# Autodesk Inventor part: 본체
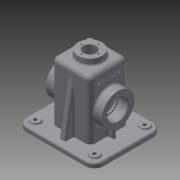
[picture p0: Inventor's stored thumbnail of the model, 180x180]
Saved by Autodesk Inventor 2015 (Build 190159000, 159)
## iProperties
Created: 2016-06
Part Number: 본체
Material: Generic
Document SubType Name: Modeling
Designer: Administrator
Density: 1 g/cm^3
Appearance: Default
Author: Administrator
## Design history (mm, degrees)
sketch "스케치1"
  geometry: L1 (-65, -57.5)-(65, -57.5); L2 (65, -57.5)-(65, 57.5); L3 (65, 57.5)-(-65, 57.5); L4 (-65, 57.5)-(-65, -57.5); L5 (-65, -57.5)-(65, 57.5); L6 (65, -57.5)-(-65, 57.5); 1 further point
  constraints: 12 end point, 2 midpoint, 2 parallel, 1 horizontal, 1 perpendicular
  dimensions: "d0" = 130 distance of L2.end L3.end; "d1" = 115 distance of L1.end L2.end
extrude "돌출1" new body sketch "스케치1" distance "d2" = 10; taper "d3" = 0 deg
fillet "모깎기1" dims "d4" = 15
fillet "모깎기2" dims "d5" = 3
sketch "스케치2"
  geometry: L1 (-50, 57.5)-(50, 57.5) reference; L2 (-65, -42.5)-(-65, 42.5) reference; L3 (50, -57.5)-(-50, -57.5) reference; L4 (65, 42.5)-(65, -42.5) reference; L5 (60, 42.5)-(60, -42.5); L6 (50, -52.5)-(-50, -52.5); L7 (-60, -42.5)-(-60, 42.5); L8 (-50, 52.5)-(50, 52.5); A1 r 15 centre (50, 42.5) between (65, 42.5) and (50, 57.5) reference; A2 r 15 centre (-50, 42.5) between (-50, 57.5) and (-65, 42.5) reference; A3 r 15 centre (-50, -42.5) between (-65, -42.5) and (-50, -57.5) reference; A4 r 15 centre (50, -42.5) between (50, -57.5) and (65, -42.5) reference; A5 r 10 centre (50, 42.5) between (60, 42.5) and (50, 52.5); A6 r 10 centre (50, -42.5) between (50, -52.5) and (60, -42.5); A7 r 10 centre (-50, -42.5) between (-60, -42.5) and (-50, -52.5); A8 r 10 centre (-50, 42.5) between (-50, 52.5) and (-60, 42.5); 1 further point
  constraints: 8 end point, 8 point on circle, 4 centre point, 7 other
  dimensions: "d6" = 120 distance between parallel lines of L5 L7
extrude "돌출2" cut sketch "스케치2" distance "d7" = 2; taper "d8" = 0 deg
sketch "스케치3"
  geometry: L1 (-32.5, -32.5)-(32.5, -32.5); L2 (32.5, -32.5)-(32.5, 32.5); L3 (32.5, 32.5)-(-32.5, 32.5); L4 (-32.5, 32.5)-(-32.5, -32.5); L5 (-32.5, -32.5)-(32.5, 32.5); L6 (32.5, -32.5)-(-32.5, 32.5); 1 further point
  constraints: 12 end point, 2 midpoint, 2 parallel, 2 perpendicular, 1 horizontal
  dimensions: "d9" = 65 distance of L2.end L3.end
extrude "돌출3" join sketch "스케치3" distance "d10" = 100; taper "d11" = 0 deg
fillet "모깎기3" dims "d12" = 8
fillet "모깎기4" dims "d13" = 8
sketch "스케치4"
  geometry: C1 r 20 at (0, 0); 1 further point
  constraints: 1 centre point, 1 coincident
  dimensions: "d14" = 40 diameter of C1
extrude "돌출4" join sketch "스케치4" distance "d15" = 10; taper "d16" = -5 deg
fillet "모깎기5" dims "d17" = 3
sketch "스케치5"
  geometry: L1 (-42.5, 0)-(42.5, 0) reference; C1 r 27.5 at (0, 55); 1 further point
  constraints: 1 centre point, 1 vertical alignment
  dimensions: "d18" = 55 diameter of C1; "d19" = 55 distance from line of C1.centre L1
extrude "돌출5" join sketch "스케치5" stored distance "d20" = 95; taper "d21" = 0 deg
fillet "모깎기6" dims "d22" = 3
sketch "스케치6"
  geometry: L1 (33.518, 89.296)-(47.5, 10); L2 (42.5, 10)-(54.5, 10) reference; L3 (57.5, 7)-(57.5, 2) reference; 1 further point
  constraints: 2 end point, 1 point on line
  dimensions: "d23" = 10 distance from line of L1.end L3; "d24" = 10 deg angle of L3 L1
feature "리브1" sketch "스케치6" dims "d25" = 1, "d26" = 10, "d27" = 0, "d28" = 0, "d29" = 1, "d30" = 1
fillet "모깎기7" dims "d31" = 3
fillet "모깎기8" dims "d32" = 3
sketch "스케치7"
  geometry: L1 (-42.5, 25.721)-(-42.5, 11.039); 1 further point
  constraints: 2 end point, 1 vertical
  dimensions: "d34" = 42.5 distance from line of L1 point (0, 0)
feature "리브2" sketch "스케치7" dims "d35" = 1, "d36" = 6, "d37" = 0, "d38" = 0, "d39" = 1, "d40" = 1
fillet "모깎기10" dims "d41" = 3
fillet "모깎기11" dims "d42" = 3
fillet "모깎기12" dims "d43" = 3
fillet "모깎기13" dims "d44" = 3
fillet "모깎기14" dims "d45" = 1
sketch "스케치8"
  geometry: C1 r 7.5 at (-50, 42.5); A1 r 12 centre (-50, 42.5) between (-50, 54.5) and (-62, 42.5) reference; 1 further point
  constraints: 1 centre point, 1 coincident
  dimensions: "d46" = 15 diameter of C1
extrude "돌출6" join sketch "스케치8" distance "d47" = 3; taper "d48" = 0 deg
fillet "모깎기15" dims "d49" = 3
hole "구멍1" diameter "d52" = 6; stored, may be unused: countersink angle "d56" = 90 deg, drill point angle "d58" = 118 deg; dims "d50" = 10, "d51" = 10, "d53" = 6, "d54" = 4, "d55" = 2, "d57" = 8
hole "구멍2" diameter "d67" = 21; stored, may be unused: countersink angle "d71" = 90 deg, drill point angle "d73" = 118 deg; dims "d65" = 10, "d66" = 10, "d68" = 6, "d69" = 4, "d70" = 2, "d72" = 8
chamfer "모따기1" distance "d74" = 1; stored, may be unused: second distance "d75" = 2, angle "d76" = 45 deg
hole "구멍3" diameter "d79" = 30; stored, may be unused: countersink angle "d83" = 90 deg, drill point angle "d85" = 118 deg; dims "d77" = 10, "d78" = 10, "d80" = 6, "d81" = 35, "d82" = 17, "d84" = 8
chamfer "모따기2" distance "d86" = 1; stored, may be unused: second distance "d87" = 2, angle "d88" = 45 deg
sketch "스케치9"
  geometry: C1 r 27.5 at (0, 0) reference; 2 further points
  constraints: 1 vertical alignment
  dimensions: "d90" = 21 distance of C1.centre point (0, 21)
hole "구멍4" sketch "스케치9" at (0, 21) diameter "d91" = 3.242; stored, may be unused: countersink angle "d95" = 90 deg, drill point angle "d97" = 118 deg; dims "d92" = 8, "d93" = 35, "d94" = 17, "d96" = 10
sketch "스케치10"
  geometry: C1 r 19.125 at (0, 0) reference; 1 further point
  constraints: 1 horizontal alignment
  dimensions: "d101" = 14.5 distance of point (14.5, 0) C1.centre
hole "구멍5" sketch "스케치10" at (14.5, 0) diameter "d102" = 2.459; stored, may be unused: countersink angle "d106" = 90 deg, drill point angle "d108" = 118 deg; dims "d103" = 7, "d104" = 35, "d105" = 17, "d107" = 9
sketch "스케치11"
  geometry: L1 (-27.5, -27.5)-(27.5, -27.5); L2 (27.5, -27.5)-(27.5, 27.5); L3 (27.5, 27.5)-(-27.5, 27.5); L4 (-27.5, 27.5)-(-27.5, -27.5); L5 (-27.5, -27.5)-(27.5, 27.5); L6 (27.5, -27.5)-(-27.5, 27.5); C1 r 10.5 at (0, 0) reference
  constraints: 12 end point, 2 midpoint, 2 parallel, 2 perpendicular, 1 horizontal
  dimensions: "d112" = 55 distance of L2.end L3.end
extrude "돌출7" cut sketch "스케치11" distance "d113" = 105; taper "d114" = 0 deg
fillet "모깎기17" dims "d115" = 3
fillet "모깎기18" dims "d116" = 3
fillet "모깎기19" dims "d117" = 0.3
fillet "모깎기20" dims "d118" = 0.3
sketch "스케치12"
  geometry: L1 (-18, 5.375)-(-18, 43.625) reference; L2 (0, -8)-(91, -8) reference; 2 further points
  constraints: 1 other
  dimensions: "d121" = 26 distance from line of point (8, 24.5) L1; "d122" = 32.5 distance from line of point (8, 24.5) L2
feature "엠보싱1" sketch "스케치12" dims "d119" = 0.5, "d120" = 0
sketch "스케치13"
  geometry: C1 r 19.125 at (0, 0) reference; C2 r 11.5 at (0, 0) reference; C3 r 20 at (0, 0)
  constraints: 1 centre point, 1 coincident
  dimensions: "d123" = 40 diameter of C3
extrude "돌출8" join sketch "스케치13" distance "d124" = 10; taper "d125" = 5 deg
fillet "모깎기21" dims "d126" = 3
node "솔리드1"
mirror "대칭1"
mirror "대칭2"
pattern_linear "직사각형 패턴1" dims "d64" = 85
mirror "대칭3"
pattern_circular "원형 패턴1" dims angle "d99" = 360 deg
mirror "대칭4"
pattern_circular "원형 패턴2" dims angle "d110" = 360 deg
